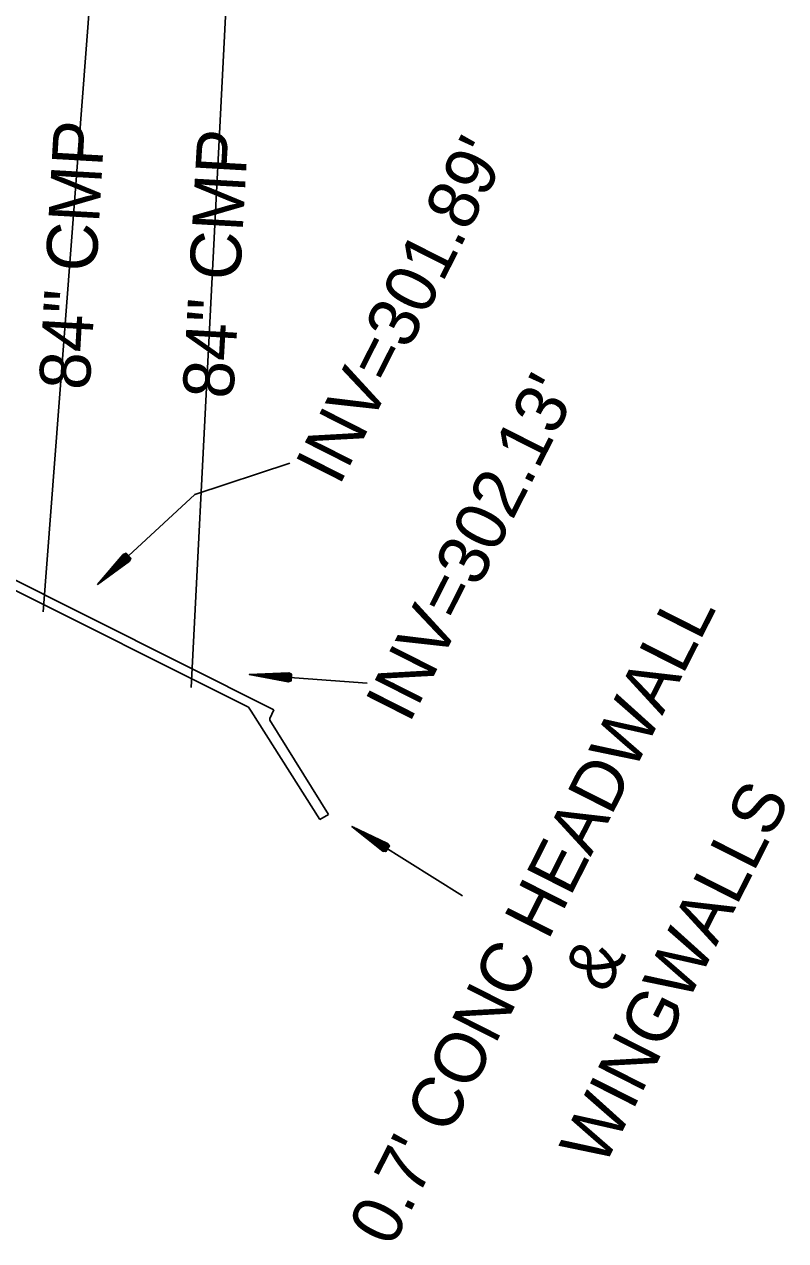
# Model space of a CAD drawing. Extents: x 1975859 to 1978323, y 778892 to 782836.
# Drawn here: x 1977955.1 to 1978015.1, y 782576.3 to 782672.2 of the extents above; entities that cross this region are included whole.
import ezdxf

# ---------------------------------------------------------------- set-up
doc = ezdxf.new("R2010")
doc.units = 0
for name, color, linetype in [('Exist Structure Major Bridge WW', 7, 'Continuous'), ('Exist Structure Major Bridge WW Text', 7, 'Continuous'), ('Exist Structure Minor Pipes CMP 84 Inch', 7, 'Continuous'), ('Exist Structure Minor Pipes CMP 84 Inch Invert', 7, 'Continuous'), ('Exist Structure Minor Pipes CMP 84 Inch SizeText', 7, 'Continuous')]:
    doc.layers.add(name, color=color, linetype=linetype)

msp = doc.modelspace()

# ---------------------------------------------------------------- linework, layer by layer
at = {"layer": 'Exist Structure Major Bridge WW'}
for p, q in [((1977974.789, 782618.155), (1977951.778, 782629.725)), ((1977952.38, 782628.608), (1977972.779, 782618.373)), ((1977972.779, 782618.373), (1977973.004, 782618.059)), ((1977973.004, 782618.059), (1977978.424, 782609.514)), ((1977974.463, 782617.356), (1977974.469, 782617.497)), ((1977979.098, 782609.915), (1977974.463, 782617.356)), ((1977974.469, 782617.497), (1977974.789, 782618.155)), ((1977978.424, 782609.514), (1977979.098, 782609.915))]:
    msp.add_line(p, q, dxfattribs=at)
at = {"layer": 'Exist Structure Major Bridge WW Text'}
for p, q in [((1977989.664, 782603.504), (1977980.941, 782608.971)), ((1977983.48, 782607.38), (1977983.829, 782607.418)), ((1977983.597, 782607.049), (1977983.48, 782607.38)), ((1977983.48, 782607.38), (1977983.839, 782607.348)), ((1977983.48, 782607.38), (1977983.782, 782607.258)), ((1977983.48, 782607.38), (1977983.722, 782607.159)), ((1977983.48, 782607.38), (1977983.672, 782607.086)), ((1977983.893, 782607.435), (1977983.61, 782606.983))]:
    msp.add_line(p, q, dxfattribs=at)
for points in [[(1977983.732, 782607.467), (1977980.941, 782608.971), (1977983.893, 782607.435), (1977983.829, 782607.418), (1977983.732, 782607.467), (1977983.48, 782607.38), (1977983.509, 782607.112), (1977983.597, 782607.049), (1977983.61, 782606.983), (1977980.941, 782608.971), (1977983.509, 782607.112)], [(1977983.893, 782607.435), (1977983.747, 782607.636), (1977980.941, 782608.971), (1977983.366, 782607.027), (1977983.61, 782606.983)], [(1977983.488, 782607.006), (1977980.941, 782608.971), (1977983.819, 782607.535)], [(1977981.083, 782608.87), (1977981.021, 782608.921), (1977981.106, 782608.882), (1977981.189, 782608.837), (1977981.1, 782608.872), (1977981.158, 782608.814), (1977981.235, 782608.759), (1977981.18, 782608.821), (1977981.271, 782608.793), (1977981.353, 782608.748), (1977981.259, 782608.772), (1977981.311, 782608.704), (1977981.387, 782608.65), (1977981.338, 782608.722), (1977981.436, 782608.704), (1977981.519, 782608.66), (1977981.417, 782608.672), (1977981.462, 782608.595), (1977981.538, 782608.54), (1977981.497, 782608.623), (1977981.601, 782608.615), (1977981.683, 782608.571), (1977981.576, 782608.573), (1977981.614, 782608.486), (1977981.689, 782608.431), (1977981.656, 782608.523), (1977981.765, 782608.527), (1977981.848, 782608.482), (1977981.735, 782608.473), (1977981.765, 782608.375), (1977981.841, 782608.32), (1977981.814, 782608.424), (1977981.931, 782608.438), (1977982.013, 782608.393), (1977981.894, 782608.374), (1977981.917, 782608.265), (1977981.993, 782608.211), (1977981.973, 782608.324), (1977982.095, 782608.348), (1977982.177, 782608.304), (1977982.052, 782608.275), (1977982.069, 782608.156), (1977982.144, 782608.101), (1977982.132, 782608.225), (1977982.26, 782608.26), (1977982.343, 782608.215), (1977982.211, 782608.175), (1977982.22, 782608.046), (1977982.296, 782607.991), (1977982.291, 782608.125), (1977982.425, 782608.171), (1977982.508, 782608.127), (1977982.37, 782608.076), (1977982.372, 782607.936), (1977982.448, 782607.881), (1977982.449, 782608.026), (1977982.59, 782608.082), (1977982.673, 782608.037), (1977982.528, 782607.976), (1977982.523, 782607.826), (1977982.6, 782607.771), (1977982.607, 782607.927), (1977982.755, 782607.993), (1977982.837, 782607.949), (1977982.687, 782607.877), (1977982.676, 782607.716), (1977982.751, 782607.662), (1977982.766, 782607.827), (1977982.92, 782607.904), (1977983.002, 782607.86), (1977982.85, 782607.785), (1977982.827, 782607.607), (1977982.903, 782607.552), (1977982.925, 782607.728), (1977983.084, 782607.816), (1977983.167, 782607.771), (1977983.004, 782607.678), (1977982.978, 782607.496), (1977983.055, 782607.442), (1977983.083, 782607.628), (1977983.249, 782607.727), (1977983.331, 782607.682), (1977983.163, 782607.579), (1977983.13, 782607.387), (1977983.206, 782607.332), (1977983.242, 782607.529), (1977983.414, 782607.638), (1977983.496, 782607.593), (1977983.322, 782607.479), (1977983.282, 782607.277), (1977983.358, 782607.222), (1977983.401, 782607.429), (1977983.579, 782607.549), (1977983.661, 782607.504), (1977983.48, 782607.38), (1977983.434, 782607.167)]]:
    msp.add_lwpolyline(points, dxfattribs=at)
at = {"layer": 'Exist Structure Minor Pipes CMP 84 Inch'}
for p, q in [((1977961.421, 782688.777), (1977956.624, 782625.902)), ((1977971.523, 782683.692), (1977968.272, 782619.938))]:
    msp.add_line(p, q, dxfattribs=at)
at = {"layer": 'Exist Structure Minor Pipes CMP 84 Inch Invert'}
for p, q in [((1977968.558, 782635.154), (1977976.062, 782637.621)), ((1977960.906, 782628.059), (1977968.558, 782635.154)), ((1977963.103, 782630.096), (1977963.156, 782630.443)), ((1977963.103, 782630.096), (1977963.226, 782630.434)), ((1977963.103, 782630.096), (1977963.299, 782630.356)), ((1977963.103, 782630.096), (1977963.379, 782630.272)), ((1977963.103, 782630.096), (1977963.436, 782630.205)), ((1977963.453, 782630.123), (1977963.103, 782630.096)), ((1977963.157, 782630.51), (1977963.519, 782630.118)), ((1977982.136, 782620.259), (1977972.855, 782620.957)), ((1977975.843, 782620.732), (1977976.133, 782620.929)), ((1977975.843, 782620.732), (1977976.175, 782620.872)), ((1977975.843, 782620.732), (1977976.167, 782620.766)), ((1977976.1, 782620.494), (1977975.843, 782620.732)), ((1977975.843, 782620.732), (1977976.16, 782620.65)), ((1977975.843, 782620.732), (1977976.15, 782620.562)), ((1977976.183, 782620.974), (1977976.143, 782620.442))]:
    msp.add_line(p, q, dxfattribs=at)
for points in [[(1977963.084, 782630.363), (1977960.906, 782628.059), (1977963.157, 782630.51), (1977963.156, 782630.443), (1977963.084, 782630.363), (1977963.103, 782630.096), (1977963.369, 782630.055), (1977963.453, 782630.123), (1977963.519, 782630.118), (1977960.906, 782628.059), (1977963.369, 782630.055)], [(1977963.157, 782630.51), (1977962.925, 782630.421), (1977960.906, 782628.059), (1977963.413, 782629.895), (1977963.519, 782630.118)], [(1977963.465, 782630.006), (1977960.906, 782628.059), (1977963.041, 782630.465)], [(1977961.04, 782628.17), (1977960.975, 782628.123), (1977961.034, 782628.196), (1977961.099, 782628.264), (1977961.043, 782628.187), (1977961.113, 782628.228), (1977961.186, 782628.288), (1977961.112, 782628.251), (1977961.163, 782628.331), (1977961.228, 782628.399), (1977961.18, 782628.314), (1977961.259, 782628.346), (1977961.331, 782628.405), (1977961.249, 782628.378), (1977961.292, 782628.468), (1977961.356, 782628.536), (1977961.318, 782628.442), (1977961.404, 782628.464), (1977961.477, 782628.524), (1977961.387, 782628.505), (1977961.421, 782628.603), (1977961.485, 782628.672), (1977961.455, 782628.569), (1977961.549, 782628.582), (1977961.622, 782628.641), (1977961.524, 782628.633), (1977961.549, 782628.739), (1977961.613, 782628.807), (1977961.592, 782628.696), (1977961.695, 782628.7), (1977961.768, 782628.759), (1977961.661, 782628.76), (1977961.678, 782628.875), (1977961.742, 782628.943), (1977961.73, 782628.824), (1977961.841, 782628.818), (1977961.913, 782628.877), (1977961.798, 782628.887), (1977961.806, 782629.012), (1977961.871, 782629.079), (1977961.867, 782628.951), (1977961.986, 782628.936), (1977962.059, 782628.995), (1977961.936, 782629.014), (1977961.935, 782629.147), (1977962, 782629.216), (1977962.004, 782629.078), (1977962.132, 782629.053), (1977962.204, 782629.113), (1977962.073, 782629.142), (1977962.064, 782629.284), (1977962.128, 782629.352), (1977962.142, 782629.205), (1977962.277, 782629.171), (1977962.35, 782629.23), (1977962.21, 782629.269), (1977962.193, 782629.419), (1977962.257, 782629.488), (1977962.279, 782629.333), (1977962.423, 782629.289), (1977962.496, 782629.348), (1977962.348, 782629.396), (1977962.321, 782629.556), (1977962.386, 782629.624), (1977962.416, 782629.46), (1977962.568, 782629.407), (1977962.641, 782629.466), (1977962.485, 782629.524), (1977962.45, 782629.692), (1977962.514, 782629.76), (1977962.548, 782629.594), (1977962.713, 782629.525), (1977962.786, 782629.583), (1977962.622, 782629.651), (1977962.579, 782629.828), (1977962.643, 782629.895), (1977962.691, 782629.715), (1977962.859, 782629.642), (1977962.932, 782629.701), (1977962.759, 782629.778), (1977962.708, 782629.964), (1977962.772, 782630.032), (1977962.828, 782629.842), (1977963.005, 782629.76), (1977963.078, 782629.819), (1977962.897, 782629.906), (1977962.836, 782630.1), (1977962.901, 782630.167), (1977962.965, 782629.969), (1977963.15, 782629.878), (1977963.223, 782629.937), (1977963.034, 782630.033), (1977962.965, 782630.236), (1977963.029, 782630.304), (1977963.103, 782630.096), (1977963.296, 782629.996)], [(1977976.183, 782620.974), (1977975.96, 782621.083), (1977972.855, 782620.957), (1977975.906, 782620.368), (1977976.143, 782620.442)], [(1977976.024, 782620.405), (1977972.855, 782620.957), (1977976.071, 782621.029)], [(1977976.025, 782620.927), (1977972.855, 782620.957), (1977976.183, 782620.974), (1977976.133, 782620.929), (1977976.025, 782620.927), (1977975.843, 782620.732), (1977975.994, 782620.509), (1977976.1, 782620.494), (1977976.143, 782620.442), (1977972.855, 782620.957), (1977975.994, 782620.509)], [(1977973.028, 782620.934), (1977972.949, 782620.95), (1977973.043, 782620.955), (1977973.136, 782620.954), (1977973.042, 782620.943), (1977973.12, 782620.92), (1977973.214, 782620.907), (1977973.136, 782620.936), (1977973.23, 782620.953), (1977973.323, 782620.952), (1977973.229, 782620.929), (1977973.306, 782620.893), (1977973.399, 782620.88), (1977973.322, 782620.922), (1977973.417, 782620.951), (1977973.511, 782620.951), (1977973.416, 782620.915), (1977973.491, 782620.867), (1977973.584, 782620.854), (1977973.509, 782620.908), (1977973.605, 782620.949), (1977973.698, 782620.949), (1977973.603, 782620.901), (1977973.676, 782620.841), (1977973.769, 782620.828), (1977973.696, 782620.894), (1977973.791, 782620.948), (1977973.885, 782620.947), (1977973.789, 782620.887), (1977973.862, 782620.814), (1977973.954, 782620.801), (1977973.882, 782620.88), (1977973.979, 782620.946), (1977974.072, 782620.945), (1977973.976, 782620.873), (1977974.048, 782620.788), (1977974.14, 782620.774), (1977974.069, 782620.866), (1977974.166, 782620.944), (1977974.259, 782620.943), (1977974.163, 782620.859), (1977974.232, 782620.761), (1977974.325, 782620.748), (1977974.256, 782620.852), (1977974.353, 782620.943), (1977974.447, 782620.941), (1977974.349, 782620.845), (1977974.418, 782620.734), (1977974.511, 782620.721), (1977974.443, 782620.838), (1977974.541, 782620.941), (1977974.634, 782620.94), (1977974.536, 782620.831), (1977974.603, 782620.708), (1977974.696, 782620.695), (1977974.629, 782620.824), (1977974.728, 782620.939), (1977974.822, 782620.938), (1977974.723, 782620.817), (1977974.788, 782620.681), (1977974.881, 782620.668), (1977974.816, 782620.809), (1977974.915, 782620.937), (1977975.009, 782620.936), (1977974.91, 782620.802), (1977974.974, 782620.655), (1977975.066, 782620.642), (1977975.003, 782620.796), (1977975.103, 782620.935), (1977975.196, 782620.934), (1977975.097, 782620.797), (1977975.159, 782620.628), (1977975.252, 782620.615), (1977975.19, 782620.782), (1977975.289, 782620.934), (1977975.383, 782620.933), (1977975.283, 782620.775), (1977975.344, 782620.602), (1977975.438, 782620.589), (1977975.376, 782620.767), (1977975.477, 782620.932), (1977975.57, 782620.931), (1977975.469, 782620.76), (1977975.53, 782620.576), (1977975.623, 782620.562), (1977975.563, 782620.753), (1977975.664, 782620.93), (1977975.758, 782620.929), (1977975.656, 782620.747), (1977975.715, 782620.549), (1977975.808, 782620.536), (1977975.75, 782620.74), (1977975.851, 782620.928), (1977975.945, 782620.927), (1977975.843, 782620.732), (1977975.9, 782620.523)]]:
    msp.add_lwpolyline(points, dxfattribs=at)

# ---------------------------------------------------------------- texts
at = {"layer": 'Exist Structure Major Bridge WW Text'}
for s, p in [("0.7' CONC HEADWALL", (1977984.099, 782575.669)), ('WINGWALLS', (1978000.759, 782581.964)), ('&', (1978000.983, 782595.691))]:
    msp.add_text(s, height=4, rotation=63.11985, dxfattribs=at).set_placement(p)
at = {"layer": 'Exist Structure Minor Pipes CMP 84 Inch Invert'}
for s, p in [("INV=301.89'", (1977979.934, 782635.739)), ("INV=302.13'", (1977985.45, 782617.004))]:
    msp.add_text(s, height=4, rotation=63.11985, dxfattribs=at).set_placement(p)
at = {"layer": 'Exist Structure Minor Pipes CMP 84 Inch SizeText'}
for p in [(1977960.264, 782643.326), (1977971.579, 782642.642)]:
    msp.add_text('84" CMP', height=4, rotation=86.74141, dxfattribs=at).set_placement(p)

doc.saveas('drawing.dxf')
